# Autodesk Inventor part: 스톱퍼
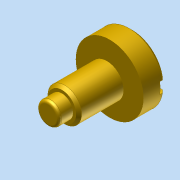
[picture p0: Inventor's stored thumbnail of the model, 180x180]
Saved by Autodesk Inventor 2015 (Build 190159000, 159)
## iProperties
Created: 2026-09
Part Number: 스톱퍼
Material: 일반
Document SubType Name: Modeling
Designer: SCD-A06
Density: 1 g/cm^3
Appearance: 기본값
Author: SCD-A06
Author: jhkim
Creation Date: 2026-08-27
Sending System: Autodesk Inventor 2027
Preprocessor: ST-DEVELOPER v20.1
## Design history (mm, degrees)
node "스톱퍼1"
node "솔리드1"
node "기준1"
